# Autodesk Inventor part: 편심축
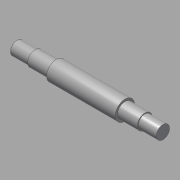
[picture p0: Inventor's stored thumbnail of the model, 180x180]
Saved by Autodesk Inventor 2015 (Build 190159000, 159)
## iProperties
Created: 2015-10
Part Number: 편심축
Document SubType Name: Modeling
Designer: mdu
Density: 1 g/cm^3
Material: 강철, 연강
Mass: 168.947 g
Surface Area: 248.524 cm^2
Volume: 168.947 cm^3
Appearance: 강철
Author: mdu
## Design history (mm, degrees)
sketch "스케치1"
  geometry: L1 (-20.5, -41.331)-(-20.5, 32.669) reference; L2 (7.5, -30.031)-(7.5, 21.369) reference; L3 (135.5, -30.331)-(135.5, 21.669) reference; L4 (121.5, 21.369)-(121.5, -30.031) reference; L5 (184.5, -4.331)-(-7.5, -4.331); L6 (184.5, -4.331)-(184.5, 6.669); L7 (154.5, 8.169)-(121.5, 8.169); L8 (121.5, 8.169)-(121.5, 11.669); L9 (121.5, 11.669)-(7.5, 11.669); L10 (7.5, 11.669)-(7.5, 8.169); L11 (7.5, 8.169)-(-7.5, 8.169); L12 (-7.5, 8.169)-(-7.5, -4.331); L13 (154.5, 8.169)-(154.5, 6.669); L14 (154.5, 6.669)-(184.5, 6.669); C1 r 32.5 at (64.5, -4.331) reference; 1 further point
  constraints: 21 end point, 8 perpendicular, 5 point on line, 1 collinear
  dimensions: "d1" = 25 diameter of L11 L5; "d2" = 32 diameter of L9 L5; "d4" = 15 distance of L10.end L11.end; "d15" = 33 distance of L7.start L7.end; "d26" = 30 distance of L13.end L6.end; "d36" = 22 diameter of L14 L5
revolve "회전1" sketch "스케치1" stored, may be unused: angle "d6" = 90 deg
node "작업 평면1"
sketch "스케치2"
  geometry: C1 r 16 at (0, 0) reference; C2 r 20.75 at (0, 4)
  constraints: 1 centre point, 1 vertical alignment
  dimensions: "d34" = 4 distance of C2.centre C1.centre; "d35" = 41.5 diameter of C2
extrude "돌출1" join sketch "스케치2" stored distance "d9" = 40; taper "d10" = 0 deg
chamfer "모따기1" distance "d11" = 1; stored, may be unused: second distance "d12" = 2, angle "d13" = 45 deg
node "작업 평면2"
sketch "스케치3"
  geometry: L1 (-15, -10)-(-15, 10) reference; L2 (-15, 3)-(0, 3); L3 (0, -3)-(-15, -3); A1 r 3 centre (0, 0) between (0, -3) and (0, 3); 2 further points
  constraints: 4 end point, 2 perpendicular, 2 point on circle, 2 point on line, 2 tangent, 1 centre point, 1 horizontal alignment, 1 midpoint
  dimensions: "d16" = 18 dimension on A1 L1; "d17" = 6 distance between parallel lines of L3 L2
extrude "돌출2" cut sketch "스케치3" distance "d18" = 3.5; taper "d19" = 0 deg
node "솔리드1"
node "참조1"
node "참조2"
node "참조3"
node "참조4"
node "참조5"
other parameters: "d30" = 35
